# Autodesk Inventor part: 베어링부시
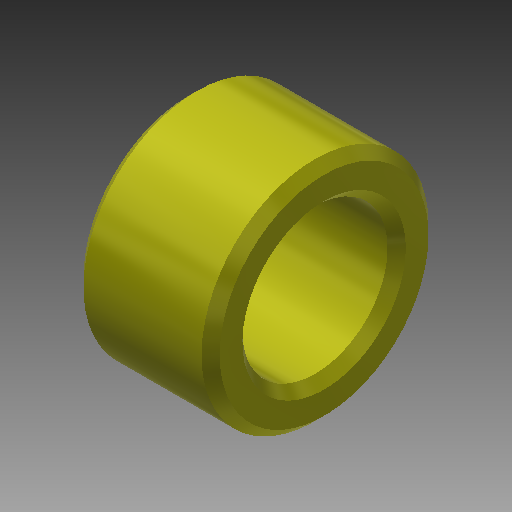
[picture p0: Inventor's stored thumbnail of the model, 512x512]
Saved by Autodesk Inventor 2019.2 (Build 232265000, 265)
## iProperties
Created: 2019-03
Part Number: 베어링부시
Material: 강철, 연강
Document SubType Name: Modeling
Designer: mduedu
Density: 1 g/cm^3
Appearance: 노란색
Author: mduedu
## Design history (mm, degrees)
sketch "스케치1"
  geometry: L1 (-7.5, 12.5)-(7.5, 12.5); L2 (7.5, 12.5)-(7.5, 8); L3 (7.5, 8)-(-7.5, 8); L4 (-7.5, 8)-(-7.5, 12.5); L5 (-7.5, 0)-(7.5, 0); 3 further points
  constraints: 10 end point, 2 midpoint, 2 parallel, 2 perpendicular, 2 vertical alignment, 1 coincident, 1 horizontal
  dimensions: "d0" = 16 diameter of L3 L5; "d2" = 25 diameter of L1 L5; "d3" = 15 distance of L1.start L1.end
revolve "회전1" sketch "스케치1" stored, may be unused: angle "d4" = 90 deg
chamfer "모따기1" distance "d5" = 1; stored, may be unused: second distance "d6" = 2, angle "d7" = 45 deg
chamfer "모따기2" distance "d8" = 1; stored, may be unused: second distance "d9" = 2, angle "d10" = 45 deg
node "솔리드1"
